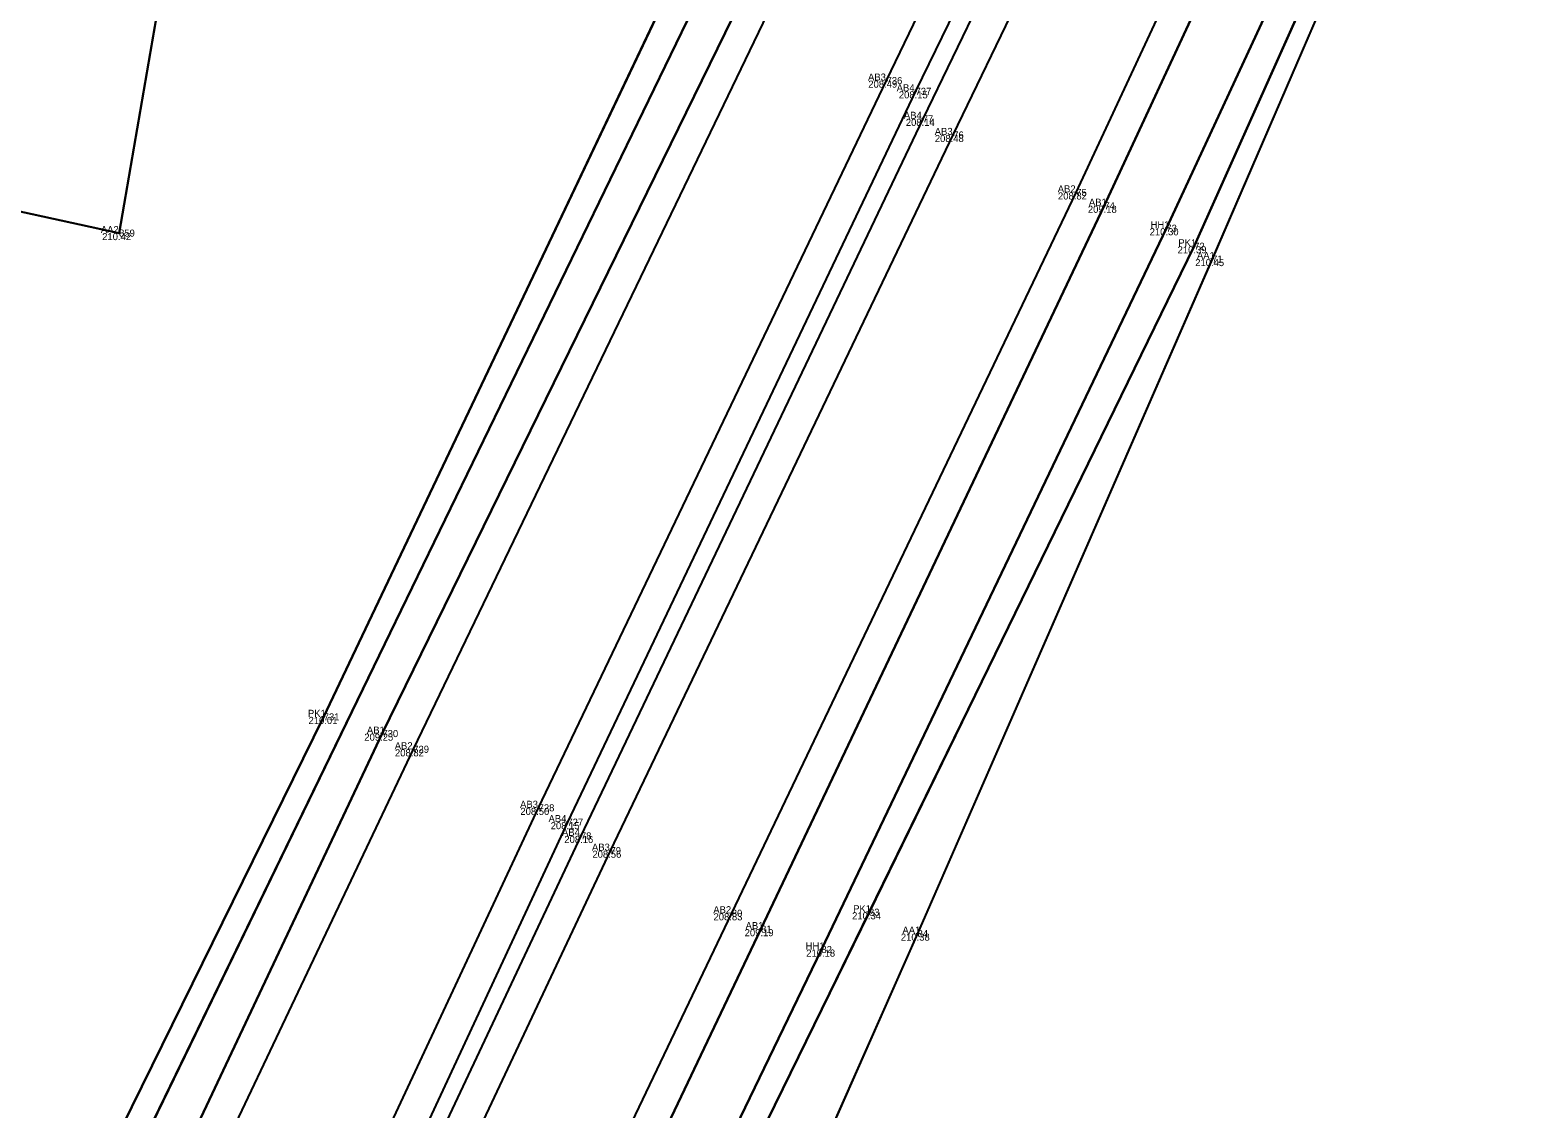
# Model space of a CAD drawing. Extents: x -263091 to -262565, y -1238731 to -1237092.
# Drawn here: x -262786.65 to -262743.97, y -1237649.19 to -1237618.65 of the extents above; entities that cross this region are included whole.
import ezdxf

# ---------------------------------------------------------------- set-up
doc = ezdxf.new("R2010")
doc.units = 0
for name, color, linetype in [('01_Hrana_betónu', 7, 'Continuous'), ('02_Oplotenie', 7, 'Continuous'), ('03_Asfalt', 7, 'Continuous'), ('05_Hrana_terénu', 7, 'Continuous'), ('Groma (21)', 7, 'Continuous'), ('Groma (22)', 7, 'Continuous'), ('Groma (23)', 7, 'Continuous'), ('Groma (24)', 7, 'Continuous'), ('U005_Betónové_panely', 7, 'Continuous'), ('U005_Zeleň_mimo', 7, 'Continuous'), ('U005_Zeleň_vnútro', 7, 'Continuous'), ('U005_Zeleň_zatrávňovač', 7, 'Continuous')]:
    doc.layers.add(name, color=color, linetype=linetype)

msp = doc.modelspace()

# ---------------------------------------------------------------- linework, layer by layer
at = {"layer": '01_Hrana_betónu'}
for points in [[(-262786.432, -1237675.911), (-262784.052, -1237670.991), (-262777.997, -1237658.39), (-262770.22, -1237641.884), (-262760.517, -1237621.621), (-262751.199, -1237602.266), (-262746.917, -1237592.345), (-262743.67, -1237583.59), (-262741.234, -1237574.416), (-262739.924, -1237566.213), (-262738.929, -1237556.596), (-262738.741, -1237547.665), (-262738.506, -1237524.618), (-262738.316, -1237501.393), (-262738.103, -1237478.98), (-262737.841, -1237459.175), (-262737.82, -1237425.07), (-262737.772, -1237401.714), (-262737.893, -1237377.738), (-262738.012, -1237356.488), (-262737.973, -1237332.295), (-262738.006, -1237318.022), (-262737.947, -1237310.645)], [(-262738.855, -1237311.192), (-262738.946, -1237318.051), (-262738.849, -1237332.413), (-262738.867, -1237356.312), (-262738.748, -1237377.69), (-262738.758, -1237401.69), (-262738.753, -1237425.185), (-262738.668, -1237459.096), (-262739.01, -1237478.875), (-262739.257, -1237501.361), (-262739.436, -1237524.506), (-262739.635, -1237547.624), (-262739.863, -1237556.5), (-262740.784, -1237566.075), (-262742.123, -1237574.161), (-262744.555, -1237583.315), (-262747.793, -1237592.067), (-262752.033, -1237601.877), (-262761.381, -1237621.164), (-262771.059, -1237641.465), (-262778.806, -1237657.918), (-262784.861, -1237670.667), (-262787.201, -1237675.529)], [(-262739.343, -1237311.485), (-262739.423, -1237318.909), (-262739.337, -1237332.42), (-262739.334, -1237355.849), (-262739.135, -1237377.701), (-262739.178, -1237401.786), (-262739.257, -1237424.031), (-262739.458, -1237458.924), (-262739.421, -1237479.296), (-262739.718, -1237500.116), (-262739.917, -1237524.824), (-262740.163, -1237546.913), (-262740.342, -1237556.649), (-262741.144, -1237564.78), (-262742.646, -1237573.838), (-262744.715, -1237582.455), (-262748.007, -1237591.229), (-262752.529, -1237601.669), (-262761.584, -1237620.386), (-262771.44, -1237641.076), (-262779.114, -1237657.574), (-262785.318, -1237670.364), (-262787.643, -1237675.31)], [(-262788.441, -1237674.914), (-262786.102, -1237669.974), (-262779.96, -1237657.146), (-262772.255, -1237640.671), (-262762.405, -1237620.082), (-262753.353, -1237601.237), (-262748.855, -1237590.92), (-262745.54, -1237582.117), (-262743.431, -1237573.688), (-262742.016, -1237564.7), (-262741.168, -1237556.501), (-262740.979, -1237546.892), (-262740.851, -1237524.752), (-262740.671, -1237500.08), (-262740.394, -1237479.483), (-262740.216, -1237458.955), (-262740.117, -1237423.647), (-262740.094, -1237401.75), (-262740.13, -1237377.708), (-262740.243, -1237355.929), (-262740.317, -1237332.345), (-262740.44, -1237318.894), (-262740.323, -1237312.076)], [(-262744.671, -1237314.693), (-262744.322, -1237332.28), (-262744.032, -1237356.103), (-262743.621, -1237377.876), (-262743.427, -1237401.834), (-262743.334, -1237423.507), (-262743.665, -1237455.163), (-262743.89, -1237458.66), (-262743.816, -1237479.543), (-262744.125, -1237500.374), (-262744.256, -1237524.891), (-262744.407, -1237545.149), (-262744.747, -1237556.085), (-262745.544, -1237564.593), (-262746.648, -1237572.023), (-262748.879, -1237581.03), (-262752.099, -1237589.665), (-262756.673, -1237599.828), (-262765.314, -1237617.226), (-262775.804, -1237639.013), (-262783.576, -1237655.372), (-262792.033, -1237673.09)], [(-262792.676, -1237672.47), (-262784.421, -1237654.971), (-262776.677, -1237638.569), (-262766.087, -1237616.912), (-262757.487, -1237599.378), (-262752.942, -1237589.379), (-262749.712, -1237580.796), (-262747.504, -1237571.715), (-262746.486, -1237564.414), (-262745.673, -1237555.98), (-262745.336, -1237545.322), (-262745.216, -1237524.737), (-262745.016, -1237500.506), (-262744.745, -1237479.418), (-262744.873, -1237458.479), (-262744.515, -1237455.206), (-262744.284, -1237423.517), (-262744.408, -1237401.828), (-262744.521, -1237377.717), (-262744.916, -1237356.111), (-262745.155, -1237332.402), (-262745.296, -1237327.881), (-262745.213, -1237324.651), (-262745.472, -1237315.175)], [(-262783.258, -1237677.486), (-262783.111, -1237677.185), (-262780.8, -1237672.534), (-262774.552, -1237659.911), (-262766.786, -1237643.656), (-262757.035, -1237623.248), (-262747.974, -1237603.808), (-262743.592, -1237593.531), (-262740.333, -1237584.524), (-262737.7, -1237574.963), (-262736.283, -1237566.732), (-262735.575, -1237556.629), (-262735.369, -1237547.722), (-262734.981, -1237524.159), (-262734.838, -1237501.704)], [(-262782.326, -1237677.959), (-262781.45, -1237675.8), (-262779.987, -1237673.099), (-262773.679, -1237660.319), (-262765.958, -1237644.106), (-262756.238, -1237623.625), (-262747.207, -1237604.197), (-262742.811, -1237593.79), (-262739.484, -1237584.835), (-262736.846, -1237575.127), (-262735.426, -1237566.88), (-262734.686, -1237556.753), (-262734.467, -1237547.755), (-262734.294, -1237524.216), (-262733.894, -1237501.859)]]:
    msp.add_lwpolyline(points, dxfattribs=at)
at = {"layer": '02_Oplotenie'}
for points in [[(-262728.456, -1237307.793), (-262728.519, -1237318.579), (-262728.768, -1237332.338), (-262729.377, -1237356.238), (-262730.032, -1237378.843), (-262730.564, -1237401.661), (-262730.923, -1237425.563), (-262730.973, -1237458.163), (-262731.252, -1237478.578), (-262731.235, -1237502.529), (-262731.31, -1237524.311), (-262731.953, -1237547.895), (-262732.188, -1237556.779), (-262732.808, -1237567.174), (-262734.162, -1237576.139), (-262736.979, -1237586.017), (-262740.293, -1237594.798), (-262745.086, -1237605.537), (-262753.698, -1237624.773), (-262762.903, -1237643.627), (-262772.016, -1237662.266), (-262776.478, -1237670.97)], [(-262793.971, -1237669.784), (-262786.051, -1237653.784), (-262778.339, -1237638.096), (-262767.839, -1237615.998), (-262759.49, -1237598.413), (-262754.828, -1237588.44), (-262751.768, -1237579.927), (-262749.971, -1237571.226), (-262749.021, -1237564.318), (-262748.215, -1237555.413), (-262747.787, -1237545.2), (-262747.818, -1237524.565), (-262747.681, -1237500.551), (-262747.391, -1237479.445), (-262747.231, -1237460.146), (-262746.875, -1237423.458), (-262747.304, -1237401.954), (-262748.156, -1237377.36), (-262748.89, -1237356.224), (-262749.247, -1237329.045)]]:
    msp.add_lwpolyline(points, dxfattribs=at)
at = {"layer": '03_Asfalt'}
for points in [[(-262724.746, -1237307.401), (-262727.828, -1237308.991), (-262728.093, -1237318.612), (-262728.491, -1237332.383), (-262729.117, -1237356.253), (-262729.803, -1237378.892), (-262730.272, -1237401.612), (-262730.633, -1237425.617), (-262730.625, -1237458.196), (-262731.018, -1237478.61), (-262730.917, -1237502.542), (-262731.001, -1237524.284), (-262731.468, -1237547.904), (-262731.892, -1237556.788), (-262732.535, -1237567.203), (-262733.679, -1237576.214), (-262736.504, -1237586.306), (-262740.104, -1237594.868), (-262744.783, -1237605.686), (-262753.189, -1237625.134), (-262761.527, -1237644.232), (-262769.984, -1237663.306), (-262774.379, -1237673.302), (-262777.928, -1237681.411)], [(-262768.342, -1237527.637), (-262773.935, -1237562.141), (-262778.136, -1237587.835), (-262781.33, -1237608.146), (-262784.132, -1237624.399), (-262787.108, -1237623.753), (-262791.777, -1237622.951)]]:
    msp.add_lwpolyline(points, dxfattribs=at)
at = {"layer": '05_Hrana_terénu'}
for points in [[(-262746.684, -1237500.449), (-262746.883, -1237524.672), (-262746.96, -1237545.219), (-262747.259, -1237555.728), (-262748.105, -1237564.398), (-262749.066, -1237571.186), (-262750.795, -1237580.085), (-262754.134, -1237588.771), (-262758.577, -1237598.887), (-262767.121, -1237616.464), (-262785.488, -1237654.334), (-262789.051, -1237662.387), (-262794.016, -1237671.765)], [(-262780.481, -1237679.127), (-262780.184, -1237678.906), (-262778.142, -1237677.63), (-262776.658, -1237673.919), (-262777.447, -1237671.687), (-262772.207, -1237661.172), (-262764.249, -1237644.683), (-262754.484, -1237624.262), (-262745.614, -1237605.143), (-262741.062, -1237594.471), (-262737.644, -1237585.61), (-262735.075, -1237575.555), (-262733.583, -1237567.143), (-262732.968, -1237556.742), (-262732.631, -1237547.918), (-262732.158, -1237524.14), (-262732.188, -1237502.434)]]:
    msp.add_lwpolyline(points, dxfattribs=at)
at = {"layer": 'Groma (21)'}
for centre in [(-262762.405, -1237620.082), (-262761.584, -1237620.386), (-262761.381, -1237621.164), (-262760.517, -1237621.621), (-262757.035, -1237623.248), (-262756.238, -1237623.625), (-262784.132, -1237624.399), (-262754.484, -1237624.262), (-262753.698, -1237624.773), (-262753.189, -1237625.134), (-262778.339, -1237638.096), (-262776.677, -1237638.569), (-262775.804, -1237639.013), (-262772.255, -1237640.671), (-262771.44, -1237641.076), (-262771.059, -1237641.465), (-262770.22, -1237641.884), (-262766.786, -1237643.656), (-262762.903, -1237643.627), (-262765.958, -1237644.106), (-262761.527, -1237644.232), (-262764.249, -1237644.683)]:
    msp.add_circle(centre, 0.01, dxfattribs=at)
at = {"layer": 'U005_Betónové_panely'}
for points in [[(-262783.28, -1237678.88), (-262786.97, -1237677.03), (-262787.74, -1237676.65), (-262788.17, -1237676.43), (-262788.97, -1237676.03), (-262792.52, -1237674.26), (-262791.95, -1237673.18), (-262792.03, -1237673.09), (-262792.68, -1237672.47), (-262784.42, -1237654.97), (-262776.68, -1237638.57), (-262766.09, -1237616.91), (-262757.49, -1237599.38), (-262752.94, -1237589.38), (-262749.71, -1237580.8), (-262747.5, -1237571.72), (-262746.49, -1237564.41), (-262745.67, -1237555.98), (-262745.34, -1237545.32), (-262745.22, -1237524.74), (-262745.02, -1237500.51)], [(-262733.89, -1237501.86), (-262734.29, -1237524.22), (-262734.47, -1237547.76), (-262734.69, -1237556.75), (-262735.43, -1237566.88), (-262736.85, -1237575.13), (-262739.48, -1237584.84), (-262742.81, -1237593.79), (-262747.21, -1237604.2), (-262756.24, -1237623.63), (-262765.96, -1237644.11), (-262773.68, -1237660.32), (-262779.99, -1237673.1), (-262781.45, -1237675.8), (-262782.33, -1237677.96), (-262782.75, -1237677.74), (-262783.28, -1237678.88)], [(-262747.21, -1237604.2), (-262756.24, -1237623.63), (-262765.96, -1237644.11), (-262773.68, -1237660.32), (-262779.99, -1237673.1), (-262781.45, -1237675.8), (-262782.33, -1237677.96), (-262782.75, -1237677.74), (-262783.28, -1237678.88), (-262786.97, -1237677.03), (-262787.74, -1237676.65), (-262788.17, -1237676.43), (-262788.97, -1237676.03), (-262792.52, -1237674.26), (-262791.95, -1237673.18), (-262792.03, -1237673.09), (-262792.68, -1237672.47), (-262784.42, -1237654.97), (-262776.68, -1237638.57), (-262766.09, -1237616.91)]]:
    msp.add_lwpolyline(points, dxfattribs=at)
at = {"layer": 'U005_Zeleň_mimo'}
for points in [[(-262747.68, -1237500.55), (-262747.82, -1237524.57), (-262747.79, -1237545.2), (-262748.22, -1237555.41), (-262749.02, -1237564.32), (-262749.97, -1237571.23), (-262751.77, -1237579.93), (-262754.83, -1237588.44), (-262759.49, -1237598.41), (-262767.84, -1237616), (-262778.34, -1237638.1), (-262786.05, -1237653.78), (-262793.97, -1237669.78), (-262795.54, -1237672.75), (-262808.34, -1237666.36), (-262793.39, -1237627.04), (-262791.78, -1237622.95), (-262787.11, -1237623.75), (-262784.13, -1237624.4), (-262781.33, -1237608.15), (-262778.14, -1237587.84), (-262773.94, -1237562.14), (-262768.34, -1237527.64), (-262757.02, -1237455.96)], [(-262744.78, -1237605.69), (-262753.19, -1237625.13), (-262761.53, -1237644.23), (-262769.98, -1237663.31), (-262774.38, -1237673.3), (-262777.93, -1237681.41), (-262780.92, -1237680.05), (-262780.48, -1237679.13), (-262780.18, -1237678.91), (-262778.14, -1237677.63), (-262776.66, -1237673.92), (-262776.48, -1237670.97), (-262772.02, -1237662.27), (-262762.9, -1237643.63), (-262753.7, -1237624.77), (-262745.09, -1237605.54)]]:
    msp.add_lwpolyline(points, dxfattribs=at)
at = {"layer": 'U005_Zeleň_vnútro'}
for points in [[(-262794.83, -1237673.1), (-262795.54, -1237672.75), (-262793.97, -1237669.78), (-262786.05, -1237653.78), (-262778.34, -1237638.1), (-262767.84, -1237616), (-262759.49, -1237598.41), (-262754.83, -1237588.44), (-262751.77, -1237579.93), (-262749.97, -1237571.23), (-262749.02, -1237564.32), (-262748.22, -1237555.41), (-262747.79, -1237545.2), (-262747.82, -1237524.57), (-262747.68, -1237500.55)], [(-262746.68, -1237500.45), (-262746.88, -1237524.67), (-262746.96, -1237545.22), (-262747.26, -1237555.73), (-262748.11, -1237564.4), (-262749.07, -1237571.19), (-262750.8, -1237580.09), (-262754.13, -1237588.77), (-262758.58, -1237598.89), (-262767.12, -1237616.46), (-262785.49, -1237654.33), (-262789.05, -1237662.39), (-262794.02, -1237671.77), (-262794.42, -1237672.24), (-262794.83, -1237673.1)], [(-262780.48, -1237679.13), (-262780.7, -1237678.43), (-262778.79, -1237677.1), (-262777.54, -1237674.56), (-262778.2, -1237673.69), (-262777.45, -1237671.69), (-262772.21, -1237661.17), (-262764.25, -1237644.68), (-262754.48, -1237624.26), (-262745.61, -1237605.14), (-262741.06, -1237594.47), (-262737.64, -1237585.61), (-262735.08, -1237575.56), (-262733.58, -1237567.14), (-262732.97, -1237556.74), (-262732.63, -1237547.92), (-262732.16, -1237524.14), (-262732.19, -1237502.43)], [(-262731.24, -1237502.53), (-262731.31, -1237524.31), (-262731.95, -1237547.9), (-262732.19, -1237556.78), (-262732.81, -1237567.17), (-262734.16, -1237576.14), (-262736.98, -1237586.02), (-262740.29, -1237594.8), (-262745.09, -1237605.54), (-262753.7, -1237624.77), (-262762.9, -1237643.63), (-262772.02, -1237662.27), (-262776.48, -1237670.97), (-262776.66, -1237673.92), (-262778.14, -1237677.63), (-262780.18, -1237678.91), (-262780.48, -1237679.13)], [(-262745.09, -1237605.54), (-262753.7, -1237624.77), (-262762.9, -1237643.63), (-262772.02, -1237662.27), (-262776.48, -1237670.97), (-262776.66, -1237673.92), (-262778.14, -1237677.63), (-262780.18, -1237678.91), (-262780.48, -1237679.13), (-262780.7, -1237678.43), (-262778.79, -1237677.1), (-262777.54, -1237674.56), (-262778.2, -1237673.69), (-262777.45, -1237671.69), (-262772.21, -1237661.17), (-262764.25, -1237644.68), (-262754.48, -1237624.26), (-262745.61, -1237605.14)], [(-262767.12, -1237616.46), (-262785.49, -1237654.33), (-262789.05, -1237662.39), (-262794.02, -1237671.77), (-262794.42, -1237672.24), (-262794.83, -1237673.1), (-262795.54, -1237672.75), (-262793.97, -1237669.78), (-262786.05, -1237653.78), (-262778.34, -1237638.1), (-262767.84, -1237616)]]:
    msp.add_lwpolyline(points, dxfattribs=at)
at = {"layer": 'U005_Zeleň_zatrávňovač'}
for points in [[(-262792.68, -1237672.47), (-262792.92, -1237672.24), (-262794.02, -1237671.77), (-262789.05, -1237662.39), (-262785.49, -1237654.33), (-262767.12, -1237616.46), (-262758.58, -1237598.89), (-262754.13, -1237588.77), (-262750.8, -1237580.09), (-262749.07, -1237571.19), (-262748.11, -1237564.4), (-262747.26, -1237555.73), (-262746.96, -1237545.22), (-262746.88, -1237524.67), (-262746.68, -1237500.45)], [(-262745.02, -1237500.51), (-262745.22, -1237524.74), (-262745.34, -1237545.32), (-262745.67, -1237555.98), (-262746.49, -1237564.41), (-262747.5, -1237571.72), (-262749.71, -1237580.8), (-262752.94, -1237589.38), (-262757.49, -1237599.38), (-262766.09, -1237616.91), (-262776.68, -1237638.57), (-262784.42, -1237654.97), (-262792.68, -1237672.47)], [(-262778.2, -1237673.69), (-262779.99, -1237673.1), (-262773.68, -1237660.32), (-262765.96, -1237644.11), (-262756.24, -1237623.63), (-262747.21, -1237604.2), (-262742.81, -1237593.79), (-262739.48, -1237584.84), (-262736.85, -1237575.13), (-262735.43, -1237566.88), (-262734.69, -1237556.75), (-262734.47, -1237547.76), (-262734.29, -1237524.22), (-262733.89, -1237501.86)], [(-262732.19, -1237502.43), (-262732.16, -1237524.14), (-262732.63, -1237547.92), (-262732.97, -1237556.74), (-262733.58, -1237567.14), (-262735.08, -1237575.56), (-262737.64, -1237585.61), (-262741.06, -1237594.47), (-262745.61, -1237605.14), (-262754.48, -1237624.26), (-262764.25, -1237644.68), (-262772.21, -1237661.17), (-262777.45, -1237671.69), (-262778.2, -1237673.69)], [(-262745.61, -1237605.14), (-262754.48, -1237624.26), (-262764.25, -1237644.68), (-262772.21, -1237661.17), (-262777.45, -1237671.69), (-262778.2, -1237673.69), (-262779.99, -1237673.1), (-262773.68, -1237660.32), (-262765.96, -1237644.11), (-262756.24, -1237623.63), (-262747.21, -1237604.2)], [(-262766.09, -1237616.91), (-262776.68, -1237638.57), (-262784.42, -1237654.97), (-262792.68, -1237672.47), (-262792.92, -1237672.24), (-262794.02, -1237671.77), (-262789.05, -1237662.39), (-262785.49, -1237654.33), (-262767.12, -1237616.46)]]:
    msp.add_lwpolyline(points, dxfattribs=at)

# ---------------------------------------------------------------- texts
at = {"layer": 'Groma (22)'}
for s, p in [('736', (-262762.405, -1237620.182)), ('737', (-262761.584, -1237620.486)), ('77', (-262761.381, -1237621.264)), ('76', (-262760.517, -1237621.721)), ('75', (-262757.035, -1237623.348)), ('74', (-262756.238, -1237623.725)), ('859', (-262784.132, -1237624.499)), ('73', (-262754.484, -1237624.362)), ('72', (-262753.698, -1237624.873)), ('71', (-262753.189, -1237625.234)), ('731', (-262778.339, -1237638.196)), ('730', (-262776.677, -1237638.669)), ('729', (-262775.804, -1237639.113)), ('728', (-262772.255, -1237640.771)), ('727', (-262771.44, -1237641.176)), ('78', (-262771.059, -1237641.565)), ('79', (-262770.22, -1237641.984)), ('80', (-262766.786, -1237643.756)), ('83', (-262762.903, -1237643.727)), ('81', (-262765.958, -1237644.206)), ('84', (-262761.527, -1237644.332)), ('82', (-262764.249, -1237644.783))]:
    msp.add_text(s, height=0.2, dxfattribs=at).set_placement(p)
at = {"layer": 'Groma (23)'}
for s, p in [('208.49', (-262762.922, -1237620.282)), ('208.15', (-262762.057, -1237620.586)), ('208.14', (-262761.859, -1237621.364)), ('208.48', (-262761.038, -1237621.821)), ('208.82', (-262757.552, -1237623.448)), ('209.18', (-262756.706, -1237623.825)), ('210.42', (-262784.61, -1237624.599)), ('210.30', (-262754.956, -1237624.462)), ('210.39', (-262754.166, -1237624.973)), ('210.45', (-262753.667, -1237625.334)), ('210.01', (-262778.768, -1237638.296)), ('209.25', (-262777.189, -1237638.769)), ('208.82', (-262776.321, -1237639.213)), ('208.50', (-262772.771, -1237640.871)), ('208.15', (-262771.913, -1237641.276)), ('208.16', (-262771.527, -1237641.665)), ('208.56', (-262770.732, -1237642.084)), ('208.83', (-262767.303, -1237643.856)), ('210.34', (-262763.381, -1237643.827)), ('209.19', (-262766.422, -1237644.306)), ('210.38', (-262762, -1237644.432)), ('210.18', (-262764.679, -1237644.883))]:
    msp.add_text(s, height=0.2, dxfattribs=at).set_placement(p)
at = {"layer": 'Groma (24)'}
for s, p in [('AB3', (-262762.929, -1237620.082)), ('AB4', (-262762.118, -1237620.386)), ('AB4', (-262761.915, -1237621.164)), ('AB3', (-262761.041, -1237621.621)), ('AB2', (-262757.559, -1237623.248)), ('AB1', (-262756.676, -1237623.625)), ('HH1', (-262754.931, -1237624.262)), ('AA2', (-262784.647, -1237624.399)), ('PK1', (-262754.145, -1237624.773)), ('AA1', (-262753.617, -1237625.134)), ('PK1', (-262778.786, -1237638.096)), ('AB1', (-262777.115, -1237638.569)), ('AB2', (-262776.328, -1237639.013)), ('AB3', (-262772.779, -1237640.671)), ('AB4', (-262771.974, -1237641.076)), ('AB4', (-262771.593, -1237641.465)), ('AB3', (-262770.744, -1237641.884)), ('AB2', (-262767.31, -1237643.656)), ('PK1', (-262763.35, -1237643.627)), ('AB1', (-262766.396, -1237644.106)), ('AA1', (-262761.955, -1237644.232)), ('HH1', (-262764.696, -1237644.683))]:
    msp.add_text(s, height=0.2, dxfattribs=at).set_placement(p)

doc.saveas('drawing.dxf')
